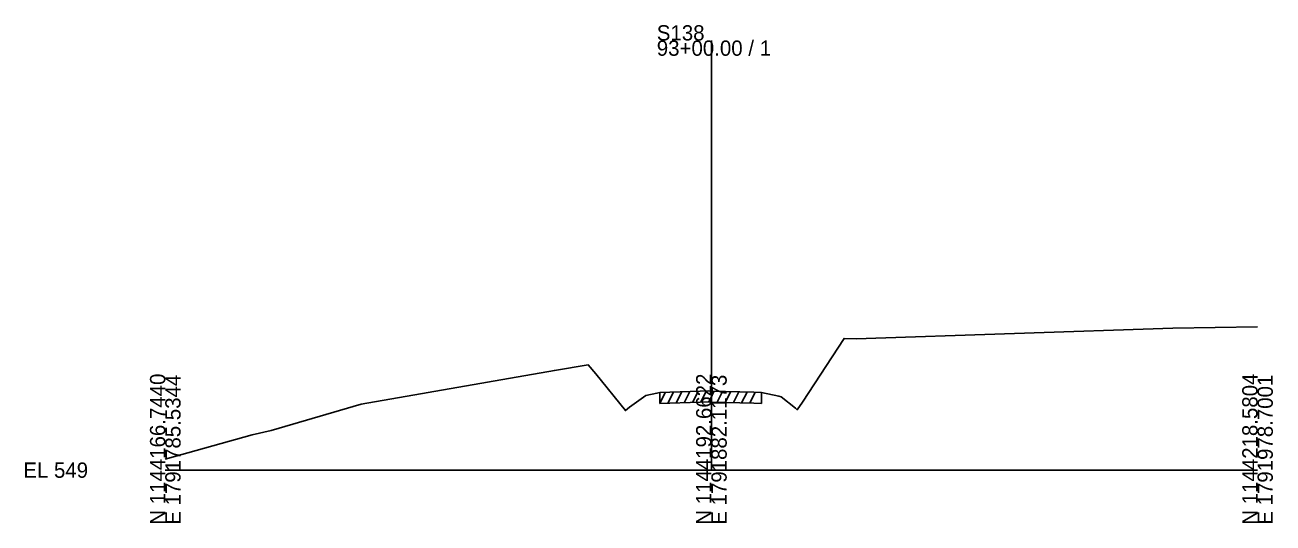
# Model space of a CAD drawing. Extents: x -26 to 1203, y -10 to 19606.
# Drawn here: x 974.3 to 1202.8, y 5990.3 to 6081.6 of the extents above; entities that cross this region are included whole.
import ezdxf

# ---------------------------------------------------------------- set-up
doc = ezdxf.new("R2010")
doc.units = 0
for name, color, linetype in [('RD_EX_Driveway', 7, 'Continuous'), ('RD_GPK_XS_Cell', 7, 'Continuous'), ('RD_XS_ExGround', 7, 'Continuous'), ('RD_XS_ExPaveRet', 7, 'Continuous')]:
    doc.layers.add(name, color=color, linetype=linetype)

msp = doc.modelspace()

# ---------------------------------------------------------------- linework, layer by layer
at = {"layer": 'RD_GPK_XS_Cell'}
for p, q in [((1100, 6000), (1100, 6078.71)), ((1000, 6000), (1100, 6000)), ((1100, 6000), (1200, 6000))]:
    msp.add_line(p, q, dxfattribs=at)
at = {"layer": 'RD_XS_ExGround'}
msp.add_lwpolyline([(1000, 6001.98), (1015.91, 6006.45), (1019.38, 6007.27), (1035.87, 6012.09), (1071.26, 6018.26), (1077.46, 6019.29), (1078.83, 6017.66), (1084.25, 6010.91), (1085.02, 6011.52), (1088.01, 6013.65), (1090.01, 6014.1), (1090.54, 6014.22), (1097.95, 6014.44), (1099.43, 6014.5), (1100, 6014.48), (1107.74, 6014.27), (1109.15, 6014.23), (1112.36, 6013.54), (1112.8, 6013.45), (1115.38, 6011.35), (1115.73, 6011.07), (1116.68, 6012.44), (1124.29, 6024.12), (1126.48, 6024.03), (1184.48, 6026.01), (1200, 6026.24)], dxfattribs=at)
at = {"layer": 'RD_XS_ExPaveRet'}
for p, q in [((1090.54, 6012.22), (1091.56, 6014.25)), ((1090.54, 6012.22), (1090.54, 6014.22)), ((1092.04, 6012.26), (1093.06, 6014.29)), ((1093.54, 6012.31), (1094.56, 6014.34)), ((1095.04, 6012.35), (1096.06, 6014.38)), ((1096.54, 6012.4), (1097.56, 6014.43)), ((1098.04, 6012.44), (1099.06, 6014.49)), ((1099.54, 6012.5), (1100.53, 6014.47)), ((1101.04, 6012.46), (1102.03, 6014.43)), ((1102.54, 6012.41), (1103.53, 6014.39)), ((1104.04, 6012.37), (1105.03, 6014.35)), ((1105.54, 6012.33), (1106.53, 6014.31)), ((1107.04, 6012.29), (1108.03, 6014.27)), ((1109.15, 6014.23), (1109.15, 6012.23)), ((1090.54, 6012.22), (1097.95, 6012.44)), ((1097.95, 6012.44), (1099.43, 6012.5)), ((1099.43, 6012.5), (1100, 6012.48)), ((1100, 6012.48), (1107.74, 6012.27)), ((1107.74, 6012.27), (1109.15, 6012.23))]:
    msp.add_line(p, q, dxfattribs=at)

# ---------------------------------------------------------------- texts
at = {"layer": 'RD_EX_Driveway'}
msp.add_text('556.24', height=0.0975, rotation=90, dxfattribs=at).set_placement((1100.1, 6014.48))
at = {"layer": 'RD_GPK_XS_Cell'}
for s, p in [('S138', (1090, 6078.71)), ('93+00.00 / 1', (1090, 6075.91)), ('EL 549', (974, 5998.6))]:
    msp.add_text(s, height=2.8, dxfattribs=at).set_placement(p)
for s, p in [('N 1144166.7440', (1000, 5990)), ('E 1791785.5344', (1002.8, 5990)), ('N 1144192.6622', (1100, 5990)), ('E 1791882.1173', (1102.8, 5990)), ('N 1144218.5804', (1200, 5990)), ('E 1791978.7001', (1202.8, 5990))]:
    msp.add_text(s, height=2.8, rotation=90, dxfattribs=at).set_placement(p)

doc.saveas('drawing.dxf')
